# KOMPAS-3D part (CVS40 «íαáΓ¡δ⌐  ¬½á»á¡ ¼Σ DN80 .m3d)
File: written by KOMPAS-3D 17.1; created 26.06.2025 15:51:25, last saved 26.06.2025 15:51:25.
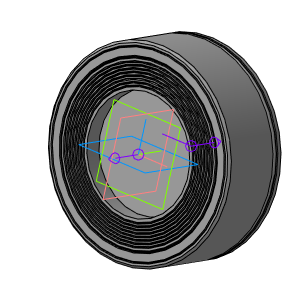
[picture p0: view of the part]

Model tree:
1. Эскиз:1
2. Элемент вращения:1
     Угол 1 = 360
3. Присоединительная точка:1
4. Присоединительная точка:2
